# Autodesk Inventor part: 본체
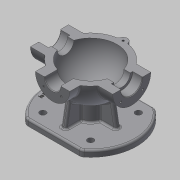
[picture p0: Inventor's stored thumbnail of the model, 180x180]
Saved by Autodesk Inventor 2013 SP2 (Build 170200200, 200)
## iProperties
Created: 2015-12
Part Number: 본체
Material: 일반
Document SubType Name: Modeling
Designer: mduedu
Density: 1 g/cm^3
Author: mduedu
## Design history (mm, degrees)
sketch "스케치1"
  geometry: L1 (-53, 0)-(53, 0); A1 r 53 centre (0, 0) between (53, 0) and (-53, 0); 2 further points
  constraints: 2 coincident, 2 end point, 2 point on circle, 1 centre point, 1 horizontal, 1 midpoint
  dimensions: "d0" = 53 radius of A1
revolve "회전1" sketch "스케치1" stored, may be unused: angle "d2" = 90 deg
feature "쉘1" dims "d11" = 10
node "작업 평면1"
sketch "스케치2"
  geometry: C1 r 31 at (0, 0); 1 further point
  constraints: 1 centre point, 1 coincident
  dimensions: "d4" = 62 diameter of C1
extrude "돌출1" join sketch "스케치2" stored distance "d5" = 10; taper "d6" = 0 deg
node "작업 평면2"
sketch "스케치3"
  geometry: C1 r 28 at (0, 0); 1 further point
  constraints: 1 centre point, 1 coincident
  dimensions: "d8" = 56 diameter of C1
extrude "돌출2" join sketch "스케치3" stored distance "d9" = 10; taper "d10" = 0 deg
hole "구멍1" diameter "d14" = 35; stored, may be unused: countersink angle "d18" = 90 deg, drill point angle "d20" = 0 deg; dims "d12" = 10, "d13" = 10, "d15" = 6, "d16" = 4, "d17" = 2, "d19" = 16
hole "구멍2" diameter "d23" = 27; stored, may be unused: countersink angle "d27" = 90 deg, drill point angle "d29" = 0 deg; dims "d21" = 10, "d22" = 10, "d24" = 6, "d25" = 4, "d26" = 2, "d28" = 16
fillet "모깎기1" dims "d30" = 0.3
hole "구멍3" diameter "d33" = 26; stored, may be unused: countersink angle "d37" = 90 deg, drill point angle "d39" = 0 deg; dims "d31" = 10, "d32" = 10, "d34" = 6, "d35" = 4, "d36" = 2, "d38" = 16
chamfer "모따기1" distance "d40" = 1; stored, may be unused: second distance "d41" = 2, angle "d42" = 45 deg
sketch "스케치4"
  geometry: L1 (0, 0)-(0, -25); L2 (0, 0)-(-17.678, -17.678); A1 r 25 centre (0, 0) between (-17.678, -17.678) and (0, -25); 1 further point
  constraints: 4 end point, 2 point on circle, 1 centre point, 1 coincident, 1 vertical
  dimensions: "d43" = 50 diameter of A1; "d47" = 45 deg angle of L1 L2
hole "구멍4" sketch "스케치4" at (-17.678, -17.678) diameter "d49" = 3.242; stored, may be unused: countersink angle "d53" = 90 deg, drill point angle "d55" = 118 deg; dims "d50" = 11, "d51" = 4, "d52" = 2, "d54" = 13
sketch "스케치5"
  geometry: L1 (0, 0)-(0, -20); L2 (0, 0)-(-14.142, -14.142); A1 r 20 centre (0, 0) between (0, -20) and (-14.142, -14.142); 2 further points
  constraints: 4 end point, 2 coincident, 2 point on circle, 1 centre point, 1 vertical
  dimensions: "d59" = 40 diameter of A1; "d65" = 45 deg angle of L1 L2
hole "구멍5" sketch "스케치5" at (-14.142, -14.142) diameter "d67" = 3.242; stored, may be unused: countersink angle "d71" = 90 deg, drill point angle "d73" = 118 deg; dims "d68" = 8, "d69" = 4, "d70" = 2, "d72" = 10
node "작업 평면3"
sketch "스케치6"
  geometry: C1 r 75 at (0, 0); 1 further point
  constraints: 1 centre point, 1 coincident
  dimensions: "d78" = 150 diameter of C1
extrude "돌출3" join sketch "스케치6" distance "d80" = 10; taper "d81" = 0 deg
sketch "스케치7"
  geometry: C1 r 20 at (0, 0); 1 further point
  constraints: 1 centre point, 1 coincident
  dimensions: "d82" = 40 diameter of C1
extrude "돌출4" join sketch "스케치7" stored distance "d84" = 10; taper "d85" = 0 deg
sketch "스케치8"
  geometry: 2 further points
  constraints: 1 coincident
hole "구멍6" sketch "스케치8" at (0, 0) diameter "d86" = 20; stored, may be unused: countersink angle "d90" = 90 deg, drill point angle "d92" = 118 deg; dims "d87" = 7, "d88" = 40, "d89" = 5, "d91" = 10
fillet "모깎기2" dims "d93" = 0.3
sketch "스케치9"
  geometry: L1 (75, -75)-(-75, -75) reference; L2 (-45, -75)-(-38.245, -36.692); A1 r 53 centre (0, 0) between (42.988, 31) and (42.988, -31) reference; 1 further point
  constraints: 2 end point, 1 point on circle, 1 point on line
  dimensions: "d94" = 45 horizontal distance of L2.start point (0, 0); "d95" = 80 deg angle of L2 L1
feature "리브1" sketch "스케치9" dims "d96" = 1, "d97" = 8, "d98" = 0, "d99" = 0, "d100" = 1, "d101" = 1
sketch "스케치14"
  geometry: L1 (-45, 110)-(45, 110); L2 (45, 110)-(45, 60); L3 (45, 60)-(-45, 60); L4 (-45, 60)-(-45, 110); L5 (-45, 110)-(45, 60); L6 (45, 110)-(-45, 60); L7 (-75, 0)-(75, 0); L8 (-45, -110)-(45, -110); L9 (45, -110)-(45, -60); L10 (45, -60)-(-45, -60); L11 (-45, -60)-(-45, -110); L12 (-45, -110)-(45, -60); L13 (45, -110)-(-45, -60); A1 r 75 centre (0, 0) between (45, 60) and (-45, 60) reference; 4 further points
  constraints: 26 end point, 5 midpoint, 5 symmetric about line, 4 point on circle, 2 parallel, 2 perpendicular, 1 coincident, 1 horizontal
  dimensions: "d151" = 15 distance edge to line of A1 L3; "d152" = 50 distance of L3.end L1.start
extrude "돌출7" cut sketch "스케치14" stored distance "d153" = 0; taper "d154" = 0 deg
fillet "모깎기9" dims "d155" = 10
sketch "스케치10"
  geometry: L1 (0, 0)-(0, -55); L2 (0, 0)-(-38.891, -38.891); A1 r 55 centre (0, 0) between (0, -55) and (-38.891, -38.891); 2 further points
  constraints: 4 end point, 2 coincident, 2 point on circle, 1 centre point, 1 vertical
  dimensions: "d105" = 110 diameter of A1; "d107" = 45 deg angle of L1 L2
hole "구멍7" sketch "스케치10" at (-38.891, -38.891) diameter "d109" = 10; stored, may be unused: countersink angle "d113" = 90 deg, drill point angle "d115" = 118 deg; dims "d110" = 7, "d111" = 40, "d112" = 5, "d114" = 10
fillet "모깎기3" dims "d120" = 3
fillet "모깎기4" dims "d121" = 3, "d122" = 3
fillet "모깎기5" dims "d123" = 3
fillet "모깎기6" dims "d124" = 3
sketch "스케치11"
  geometry: 2 further points
  constraints: 1 vertical alignment, 1 other
  dimensions: "d157" = 63 distance of point (0, 63) point (0, 0)
feature "엠보싱1" sketch "스케치11" dims "d125" = 0.5, "d126" = 0
sketch "스케치12"
  geometry: L1 (0, 100)-(0, -100); L2 (0, 100)-(100, 100); L3 (100, 100)-(100, -100); L4 (100, -100)-(0, -100); 2 further points
  constraints: 8 end point, 3 perpendicular, 1 coincident, 1 midpoint, 1 vertical
  dimensions: "d127" = 200 distance of L2.end L3.end; "d129" = 100 distance between parallel lines of L1 L3
extrude "돌출5" cut sketch "스케치12" stored distance "d130" = 10; taper "d131" = 0 deg
sketch "스케치13"
  geometry: C1 r 7 at (0, 53); A1 r 53 centre (0, 0) between (42.113, 32.179) and (-42.113, 32.179) reference; 1 further point
  constraints: 1 centre point, 1 point on circle
  dimensions: "d132" = 14 diameter of C1
extrude "돌출6" join sketch "스케치13" distance "d134" = 15; taper "d135" = 0 deg; dims "d29" = 0
hole "구멍8" diameter "d139" = 3.242; stored, may be unused: countersink angle "d143" = 90 deg, drill point angle "d145" = 118 deg; dims "d140" = 8, "d141" = 4, "d142" = 2, "d144" = 10, "d148" = 10, "d149" = 10
fillet "모깎기7" dims "d146" = 3
fillet "모깎기8" dims "d147" = 3
node "솔리드1"
mirror "대칭1"
mirror "대칭2"
pattern_circular "원형 패턴1" dims angle "d57" = 360 deg
mirror "대칭3"
pattern_circular "원형 패턴2" dims angle "d75" = 360 deg
pattern_circular "원형 패턴3" dims angle "d103" = 360 deg
pattern_circular "원형 패턴4" dims angle "d118" = 360 deg
other parameters: "d3" = 67, "d7" = 62, "d77" = -85
